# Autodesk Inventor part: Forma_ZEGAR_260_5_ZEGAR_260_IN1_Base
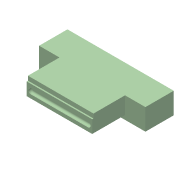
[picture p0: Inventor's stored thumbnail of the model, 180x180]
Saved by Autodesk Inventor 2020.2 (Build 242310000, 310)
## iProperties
Created: 2015-01
Part Number: Forma_ZEGAR_260_5_ZEGAR_260_IN1_Base
Material: Ogólny
Document SubType Name: Modeling
Designer: F.Stasiak
Density: 1 g/cm^3
Appearance: Domyślna
Catalog Web Link: www.expertbooks.pl
Manager: www.cadconsulting.pl
Company: Fabian Stasiak CAD Consulting
Author: F.Stasiak
Subject: Zbiór ćwiczeń. Autodesk Inventor 2020. Kurs Professional
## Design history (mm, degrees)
node "Forma_ZEGAR_260_4_ZEGAR_260_MP"
feature "Bryła5::Forma_ZEGAR_260_4_ZEGAR_260_MP"
tag "Bryła wyprowadzona1"
node "Bryła1"
feature "Forma_ZEGAR_260_4_ZEGAR_260_MP_Bodies"
